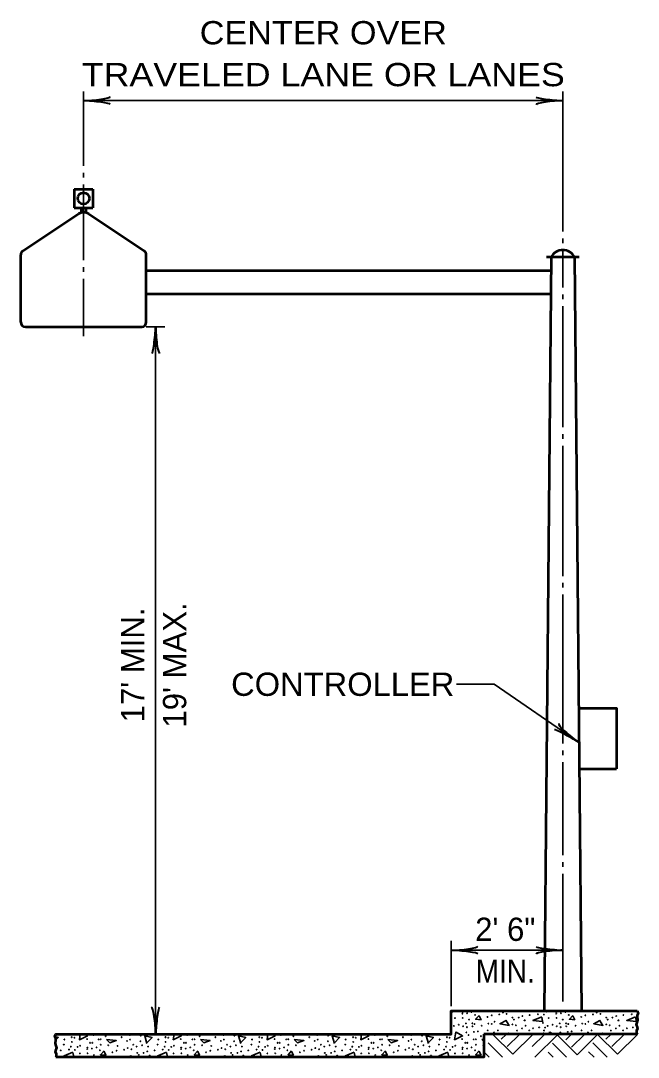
# Model space of a CAD drawing. Extents: x -1 to 679, y 1 to 441.
# Drawn here: x 304.9 to 371.2, y 249.5 to 360.9 of the extents above; entities that cross this region are included whole.
import ezdxf
from ezdxf.enums import TextEntityAlignment as Align

# ---------------------------------------------------------------- set-up
doc = ezdxf.new("R2010")
doc.units = 0
doc.layers.add('1', color=7, linetype='Continuous', lineweight=35)

msp = doc.modelspace()

# ---------------------------------------------------------------- linework, layer by layer
at = {"layer": '1'}
for p, q in [((311.626, 353.314), (311.626, 345.314)), ((363.14, 338.259), (363.14, 353.314)), ((311.626, 352.314), (363.14, 352.314)), ((311.626, 344.564), (311.626, 344.064)), ((311.626, 340.314), (311.626, 335.164)), ((363.14, 337.009), (363.14, 337.509)), ((363.14, 336.259), (363.14, 332.233)), ((311.626, 334.414), (311.626, 333.914)), ((311.626, 333.164), (311.626, 328.015)), ((363.14, 330.983), (363.14, 331.483)), ((363.14, 330.233), (363.14, 317.233)), ((311.626, 328.015), (311.626, 327.015)), ((318.376, 328.015), (320.376, 328.015)), ((319.376, 328.015), (319.376, 252.015)), ((363.14, 315.983), (363.14, 316.483)), ((363.14, 315.233), (363.14, 301.233)), ((363.14, 299.983), (363.14, 300.483)), ((363.14, 299.233), (363.14, 283.233)), ((363.14, 281.983), (363.14, 282.483)), ((363.14, 281.233), (363.14, 271.233)), ((363.14, 269.983), (363.14, 270.483)), ((363.14, 269.233), (363.14, 255.515)), ((351.14, 255.015), (351.14, 262.015)), ((351.14, 261.015), (363.14, 261.015)), ((355.62, 251.975), (357.76, 249.835)), ((357.04, 251.975), (356.52, 251.455)), ((358.48, 251.975), (357.16, 250.655)), ((359.9, 251.975), (357.76, 249.835)), ((361.18, 251.975), (359.86, 250.655)), ((362.6, 251.975), (360.14, 249.515)), ((361.676, 252.015), (361.707, 252.232)), ((361.747, 252.212), (362.091, 252.015)), ((362.5, 251.975), (364.7, 249.775)), ((364.02, 251.975), (363.46, 251.395)), ((365.46, 251.975), (364.08, 250.595)), ((366.88, 251.975), (364.7, 249.775)), ((366.88, 251.975), (369.02, 249.835)), ((368.3, 251.975), (367.78, 251.455)), ((369.74, 251.975), (368.42, 250.655)), ((371.16, 251.975), (369.02, 249.835)), ((354.427, 251.432), (354.64, 251.407)), ((354.64, 251.219), (354.427, 251.432)), ((355.1, 251.075), (356.66, 249.515)), ((362.02, 251.015), (363.536, 249.515)), ((366.36, 251.075), (367.92, 249.515)), ((316.727, 249.672), (316.441, 249.515)), ((316.8, 249.515), (316.687, 249.692)), ((326.807, 249.672), (326.521, 249.515)), ((326.88, 249.515), (326.767, 249.692)), ((336.887, 249.672), (336.601, 249.515)), ((336.96, 249.515), (336.847, 249.692)), ((346.967, 249.672), (346.681, 249.515)), ((347.041, 249.515), (346.927, 249.692)), ((354.64, 250.115), (355.24, 249.515)), ((361.56, 250.055), (362.1, 249.515)), ((365.9, 250.115), (366.5, 249.515))]:
    msp.add_line(p, q, dxfattribs=at)
at = {"layer": '1', "lineweight": 53}
for p, q in [((310.626, 342.814), (312.626, 342.814)), ((310.626, 342.814), (310.626, 340.814)), ((312.626, 342.814), (312.626, 340.814)), ((305.098, 336.164), (311.071, 340.146)), ((310.626, 340.814), (312.626, 340.814)), ((311.376, 340.814), (311.376, 340.282)), ((311.876, 340.814), (311.876, 340.282)), ((312.18, 340.146), (318.153, 336.164)), ((304.876, 328.515), (304.876, 335.748)), ((318.376, 328.515), (318.376, 335.748)), ((361.89, 335.515), (361.14, 254.515)), ((361.39, 335.515), (364.89, 335.515)), ((364.39, 335.515), (365.14, 254.515)), ((361.876, 334.015), (318.376, 334.015)), ((361.853, 331.515), (318.376, 331.515)), ((305.376, 328.015), (317.876, 328.015)), ((364.899, 280.514), (368.899, 280.514)), ((371.14, 252.015), (354.64, 252.015))]:
    msp.add_line(p, q, dxfattribs=at)
at = {"layer": '1'}
for points in [[(311.626, 343.314), (311.626, 340.814), (311.626, 340.314)], [(364.824, 283.382), (355.764, 289.594), (351.711, 289.594)], [(354.147, 253.992), (353.767, 253.592), (354.347, 253.552), (354.147, 253.952)], [(364.227, 253.992), (363.847, 253.592), (364.427, 253.552), (364.227, 253.952)], [(357.047, 253.472), (356.387, 253.112), (357.367, 252.932), (357.007, 253.492)], [(360.867, 253.852), (359.927, 253.472), (360.967, 253.352), (360.867, 253.812)], [(367.127, 253.472), (366.467, 253.112), (367.447, 252.932), (367.087, 253.492)], [(370.947, 253.852), (370.007, 253.472), (371.047, 253.352), (370.947, 253.812)], [(311.691, 252.015), (312.047, 251.812), (311.187, 251.392), (311.276, 252.015)], [(318.447, 251.012), (318.207, 251.812), (318.987, 251.652), (318.427, 251.052)], [(321.771, 252.015), (322.127, 251.812), (321.267, 251.392), (321.356, 252.015)], [(328.527, 251.012), (328.287, 251.812), (329.067, 251.652), (328.507, 251.052)], [(331.851, 252.015), (332.207, 251.812), (331.347, 251.392), (331.436, 252.015)], [(338.607, 251.012), (338.367, 251.812), (339.147, 251.652), (338.587, 251.052)], [(341.931, 252.015), (342.287, 251.812), (341.427, 251.392), (341.516, 252.015)], [(348.687, 251.012), (348.447, 251.812), (349.227, 251.652), (348.667, 251.052)], [(351.667, 252.212), (352.367, 251.812), (351.507, 251.392), (351.627, 252.232)], [(308.529, 251.729), (308.907, 251.652), (308.657, 251.384)], [(310.467, 250.052), (309.527, 249.672), (310.567, 249.552), (310.467, 250.012)], [(313.827, 250.192), (313.447, 249.792), (314.027, 249.752), (313.827, 250.152)], [(320.547, 250.052), (319.607, 249.672), (320.647, 249.552), (320.547, 250.012)], [(323.907, 250.192), (323.527, 249.792), (324.107, 249.752), (323.907, 250.152)], [(330.627, 250.052), (329.687, 249.672), (330.727, 249.552), (330.627, 250.012)], [(333.987, 250.192), (333.607, 249.792), (334.187, 249.752), (333.987, 250.152)], [(340.707, 250.052), (339.767, 249.672), (340.807, 249.552), (340.707, 250.012)], [(344.067, 250.192), (343.687, 249.792), (344.267, 249.752), (344.067, 250.152)], [(350.787, 250.052), (349.847, 249.672), (350.887, 249.552), (350.787, 250.012)], [(354.147, 250.192), (353.767, 249.792), (354.347, 249.752), (354.147, 250.152)]]:
    msp.add_lwpolyline(points, dxfattribs=at)
at = {"layer": '1', "lineweight": 53}
for points in [[(364.839, 287.014), (368.899, 287.014), (368.899, 280.514)], [(308.64, 249.515), (308.731, 249.647), (308.736, 249.86), (308.627, 250.105), (308.643, 250.247), (308.758, 250.519), (308.632, 250.863), (308.605, 251.021), (308.66, 251.359), (308.643, 251.517), (308.529, 251.73), (308.64, 252.015), (351.14, 252.015), (351.14, 254.515), (371.14, 254.515)], [(371.14, 254.515), (371.25, 254.23), (371.136, 254.017), (371.12, 253.859), (371.174, 253.521), (371.147, 253.363), (371.021, 253.019), (371.136, 252.747), (371.152, 252.605), (371.043, 252.36), (371.049, 252.147), (371.14, 252.015)], [(354.64, 252.015), (354.64, 249.515), (308.64, 249.515)]]:
    msp.add_lwpolyline(points, dxfattribs=at)
at = {"layer": '1'}
for points in [[(314.107, 251.432), (315.147, 251.312), (314.467, 251.072)], [(324.187, 251.432), (325.227, 251.312), (324.547, 251.072)], [(334.267, 251.432), (335.307, 251.312), (334.627, 251.072)], [(344.347, 251.432), (345.387, 251.312), (344.707, 251.072)]]:
    msp.add_lwpolyline(points, close=True, dxfattribs=at)
at = {"layer": '1', "lineweight": 53}
msp.add_circle((311.626, 341.813), 0.625, dxfattribs=at)
at = {"layer": '1'}
for centre in [(351.3, 254.428), (352.347, 254.195), (352.36, 254.362), (352.85, 254.248), (353.341, 254.375), (353.706, 254.062), (355.495, 254.022), (356.304, 254.115), (356.701, 254.309), (357.099, 254.181), (357.656, 254.468), (358.795, 253.943), (358.888, 254.468), (359.577, 254.049), (360.465, 254.142), (360.677, 254.455), (361.101, 254.102), (361.38, 254.428), (362.427, 254.195), (362.44, 254.362), (362.93, 254.248), (363.421, 254.375), (363.786, 254.062), (365.575, 254.022), (366.384, 254.115), (366.781, 254.309), (367.179, 254.181), (367.736, 254.468), (368.875, 253.943), (368.968, 254.468), (369.657, 254.049), (370.545, 254.142), (370.757, 254.455), (351.432, 252.882), (351.551, 253.731), (351.962, 253.002), (352.386, 253.744), (352.413, 252.856), (352.731, 253.147), (353.062, 253.558), (353.42, 253.161), (353.433, 252.842), (353.653, 253.081), (354.435, 252.909), (355.045, 253.85), (355.151, 253.134), (355.495, 253.094), (355.813, 253.333), (357.722, 253.784), (357.722, 253.041), (357.881, 253.572), (358.106, 252.949), (358.398, 253.784), (359.021, 253.479), (359.074, 253.479), (359.14, 252.895), (360.995, 253.214), (361.512, 252.882), (361.631, 253.731), (362.042, 253.002), (362.466, 253.744), (362.493, 252.856), (362.811, 253.147), (363.142, 253.558), (363.5, 253.161), (363.513, 252.842), (363.733, 253.081), (364.515, 252.909), (365.125, 253.85), (365.231, 253.134), (365.575, 253.094), (365.893, 253.333), (367.802, 253.784), (367.802, 253.041), (367.961, 253.572), (368.186, 252.949), (368.478, 253.784), (369.101, 253.479), (369.154, 253.479), (369.22, 252.895), (312.689, 251.901), (314.022, 251.782), (316.593, 251.901), (317.773, 251.835), (322.769, 251.901), (324.102, 251.782), (326.673, 251.901), (327.853, 251.835), (332.849, 251.901), (334.182, 251.782), (336.753, 251.901), (337.933, 251.835), (342.929, 251.901), (344.262, 251.782), (346.833, 251.901), (348.013, 251.835), (352.784, 252.193), (352.837, 252.75), (353.009, 251.901), (353.592, 252.246), (354.011, 252.299), (354.342, 251.782), (355.071, 252.405), (355.76, 252.193), (356.158, 252.405), (357.324, 252.074), (358.225, 252.378), (358.769, 252.617), (359.537, 252.405), (359.948, 252.63), (360.598, 252.723), (361.062, 252.087), (361.128, 252.392), (361.234, 252.71), (362.864, 252.193), (362.917, 252.75), (363.672, 252.246), (364.091, 252.299), (365.151, 252.405), (365.84, 252.193), (366.238, 252.405), (367.404, 252.074), (368.305, 252.378), (368.849, 252.617), (369.617, 252.405), (370.028, 252.63), (370.678, 252.723), (309.509, 250.88), (309.575, 251.424), (310.277, 250.655), (310.357, 251.676), (310.37, 251.159), (310.648, 251.61), (310.98, 250.628), (311.258, 250.748), (312, 251.464), (312.331, 251.066), (312.557, 251.066), (313.253, 251.435), (313.479, 251.45), (313.479, 250.854), (314.287, 250.814), (315.281, 250.735), (315.719, 251.676), (316.315, 251.265), (316.633, 251.411), (316.978, 250.867), (317.336, 250.668), (317.733, 251.238), (317.919, 250.814), (318.568, 250.668), (319.589, 250.88), (319.655, 251.424), (320.357, 250.655), (320.437, 251.676), (320.45, 251.159), (320.728, 251.61), (321.06, 250.628), (321.338, 250.748), (322.08, 251.464), (322.411, 251.066), (322.637, 251.066), (323.333, 251.435), (323.559, 251.45), (323.559, 250.854), (324.367, 250.814), (325.361, 250.735), (325.799, 251.676), (326.395, 251.265), (326.713, 251.411), (327.058, 250.867), (327.416, 250.668), (327.813, 251.238), (327.999, 250.814), (328.648, 250.668), (329.669, 250.88), (329.735, 251.424), (330.437, 250.655), (330.517, 251.676), (330.53, 251.159), (330.808, 251.61), (331.14, 250.628), (331.418, 250.748), (332.16, 251.464), (332.491, 251.066), (332.717, 251.066), (333.413, 251.435), (333.639, 251.45), (333.639, 250.854), (334.447, 250.814), (335.441, 250.735), (335.879, 251.676), (336.475, 251.265), (336.793, 251.411), (337.138, 250.867), (337.496, 250.668), (337.893, 251.238), (338.079, 250.814), (338.728, 250.668), (339.749, 250.88), (339.815, 251.424), (340.517, 250.655), (340.597, 251.676), (340.61, 251.159), (340.888, 251.61), (341.22, 250.628), (341.498, 250.748), (342.24, 251.464), (342.571, 251.066), (342.797, 251.066), (343.493, 251.435), (343.719, 251.45), (343.719, 250.854), (344.527, 250.814), (345.521, 250.735), (345.959, 251.676), (346.555, 251.265), (346.873, 251.411), (347.218, 250.867), (347.576, 250.668), (347.973, 251.238), (348.159, 250.814), (348.808, 250.668), (349.829, 250.88), (349.895, 251.424), (350.597, 250.655), (350.677, 251.676), (350.69, 251.159), (350.968, 251.61), (351.3, 250.628), (351.578, 250.748), (352.32, 251.464), (352.651, 251.066), (352.877, 251.066), (353.573, 251.435), (353.799, 251.45), (353.799, 250.854), (354.607, 250.814), (309.177, 250.249), (310.065, 250.342), (310.701, 250.302), (311.231, 249.931), (312.027, 250.395), (312.04, 250.562), (312.066, 249.944), (312.53, 250.448), (312.742, 249.758), (313.021, 250.575), (313.386, 250.262), (314.725, 250.05), (315.175, 250.222), (315.984, 250.315), (316.381, 250.509), (316.779, 250.381), (317.402, 249.984), (317.561, 249.772), (318.078, 249.984), (318.475, 250.143), (318.701, 249.679), (318.754, 249.679), (319.257, 250.249), (320.145, 250.342), (320.781, 250.302), (321.311, 249.931), (322.107, 250.395), (322.12, 250.562), (322.146, 249.944), (322.61, 250.448), (322.822, 249.758), (323.101, 250.575), (323.466, 250.262), (324.805, 250.05), (325.255, 250.222), (326.064, 250.315), (326.461, 250.509), (326.859, 250.381), (327.482, 249.984), (327.641, 249.772), (328.158, 249.984), (328.555, 250.143), (328.781, 249.679), (328.834, 249.679), (329.337, 250.249), (330.225, 250.342), (330.861, 250.302), (331.391, 249.931), (332.187, 250.395), (332.2, 250.562), (332.226, 249.944), (332.69, 250.448), (332.902, 249.758), (333.181, 250.575), (333.546, 250.262), (334.885, 250.05), (335.335, 250.222), (336.144, 250.315), (336.541, 250.509), (336.939, 250.381), (337.562, 249.984), (337.721, 249.772), (338.238, 249.984), (338.635, 250.143), (338.861, 249.679), (338.914, 249.679), (339.417, 250.249), (340.305, 250.342), (340.941, 250.302), (341.471, 249.931), (342.267, 250.395), (342.28, 250.562), (342.306, 249.944), (342.77, 250.448), (342.982, 249.758), (343.261, 250.575), (343.626, 250.262), (344.965, 250.05), (345.415, 250.222), (346.224, 250.315), (346.621, 250.509), (347.019, 250.381), (347.642, 249.984), (347.801, 249.772), (348.318, 249.984), (348.715, 250.143), (348.941, 249.679), (348.994, 249.679), (349.497, 250.249), (350.385, 250.342), (351.021, 250.302), (351.551, 249.931), (352.347, 250.395), (352.36, 250.562), (352.386, 249.944), (352.85, 250.448), (353.062, 249.758), (353.341, 250.575), (353.706, 250.262)]:
    msp.add_circle(centre, 0.0265, dxfattribs=at)
at = {"layer": '1', "lineweight": 53}
for centre, radius, start, end in [((311.626, 339.314), 1, 56.30808, 123.69007), ((305.376, 335.748), 0.5, 123.69239, 180), ((317.876, 335.748), 0.5, 0, 56.30661), ((363.14, 334.836), 1.423, 28.52934, 151.47066), ((305.376, 328.515), 0.5, 180, 270), ((317.876, 328.515), 0.5, 270, 0)]:
    msp.add_arc(centre, radius, start, end, dxfattribs=at)
at = {"layer": '1'}
for centre, start, end in [((355.601, 254.535), 226.35082, 313.64918), ((365.681, 254.535), 226.35082, 313.64918), ((371.181, 254.102), 61.61934, 241.7845), ((371.075, 253.214), 32.83014, 287.06312), ((309.416, 252.034), 223.9797, 316.0203), ((309.933, 252.007), 162.01481, 17.98519), ((314.698, 252.007), 162.01481, 17.98519), ((319.496, 252.034), 223.9797, 316.0203), ((320.013, 252.007), 162.01481, 17.98519), ((324.778, 252.007), 162.01481, 17.98519), ((329.576, 252.034), 223.9797, 316.0203), ((330.093, 252.007), 162.01481, 17.98519), ((334.858, 252.007), 162.01481, 17.98519), ((339.656, 252.034), 223.9797, 316.0203), ((340.173, 252.007), 162.01481, 17.98519), ((344.938, 252.007), 162.01481, 17.98519), ((349.736, 252.034), 223.9797, 316.0203), ((350.253, 252.007), 162.01481, 17.98519), ((351.154, 252.71), 237.37076, 122.62924), ((355.018, 252.007), 17.98519, 162.01481), ((359.816, 252.034), 316.0203, 223.9797), ((360.333, 252.007), 17.98519, 162.01481), ((365.098, 252.007), 17.98519, 162.01481), ((369.896, 252.034), 316.0203, 223.9797), ((370.413, 252.007), 17.98519, 162.01481), ((315.493, 249.533), 318.30023, 221.69977), ((325.573, 249.533), 318.30023, 221.69977), ((335.653, 249.533), 318.30023, 221.69977), ((345.733, 249.533), 318.30023, 221.69977)]:
    msp.add_arc(centre, 0.0265, start, end, dxfattribs=at)
at = {"layer": '1', "lineweight": 40}
for centre, major_axis, ratio, start_param, end_param in [((312.746, 352.102), (-1.756, 0.176), 0.07063, 3.1407148, 5.41811), ((312.746, 352.102), (-1.756, 0.176), 0.07063, 3.1407148, 5.41811), ((312.717, 352.59), (-1.786, -0.156), 0.122415, 0.8963533, 3.1415927), ((312.717, 352.59), (-1.786, -0.156), 0.122415, 0.8963533, 3.1415927), ((362.048, 352.037), (1.786, 0.156), 0.122415, 0.8963533, 3.1415927), ((362.019, 352.525), (1.756, -0.176), 0.07063, 3.1407148, 5.41811), ((319.164, 326.895), (0.176, 1.756), 0.07063, 3.1407148, 5.41811), ((319.652, 326.924), (-0.156, 1.786), 0.122415, 0.8963533, 3.1415927), ((364.08, 284.227), (1.384, -1.139), 0.122415, 3.1415927, 5.386832), ((364.08, 284.227), (1.384, -1.139), 0.122415, 3.1415927, 5.386832), ((363.78, 283.842), (-1.548, 0.848), 0.07063, 4.006668, 6.2840632), ((363.78, 283.842), (-1.548, 0.848), 0.07063, 4.006668, 6.2840632), ((352.26, 260.804), (-1.756, 0.176), 0.07063, 3.1407148, 5.41811), ((352.26, 260.804), (-1.756, 0.176), 0.07063, 3.1407148, 5.41811), ((352.231, 261.292), (-1.786, -0.156), 0.122415, 0.8963533, 3.1415927), ((352.231, 261.292), (-1.786, -0.156), 0.122415, 0.8963533, 3.1415927), ((362.048, 260.739), (1.786, 0.156), 0.122415, 0.8963533, 3.1415927), ((362.019, 261.227), (1.756, -0.176), 0.07063, 3.1407148, 5.41811), ((319.099, 253.107), (0.156, -1.786), 0.122415, 0.8963533, 3.1415927), ((319.587, 253.136), (-0.176, -1.756), 0.07063, 3.1407148, 5.41811)]:
    msp.add_ellipse(centre, major_axis=major_axis, ratio=ratio, start_param=start_param, end_param=end_param, dxfattribs=at)

# ---------------------------------------------------------------- texts
at = {"layer": '1'}
for s, width, p in [('CENTER OVER', 1.1, (337.395, 358.366)), ('TRAVELED LANE OR LANES', 1.15, (337.395, 353.866)), ('MIN.', 0.9, (356.954, 257.52))]:
    msp.add_text(s, height=2.5, dxfattribs=dict(at, width=width)).set_placement(p, align=Align.CENTER)
for s, p in [("17' MIN.", (318.166, 291.674)), ("19' MAX.", (322.666, 291.674))]:
    msp.add_text(s, height=2.5, rotation=90, dxfattribs=at).set_placement(p, align=Align.CENTER)
at = {"layer": '1', "width": 1.05}
msp.add_text('CONTROLLER', height=2.5, dxfattribs=at).set_placement((327.488, 288.351))
at = {"layer": '1'}
msp.add_text('2\' 6"', height=2.5, dxfattribs=at).set_placement((356.954, 262.02), align=Align.CENTER)

doc.saveas('drawing.dxf')
